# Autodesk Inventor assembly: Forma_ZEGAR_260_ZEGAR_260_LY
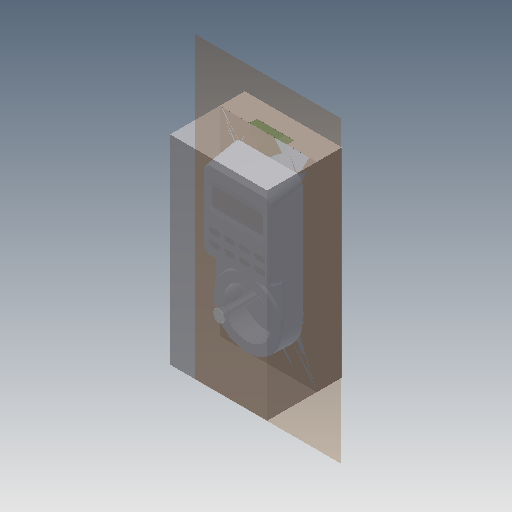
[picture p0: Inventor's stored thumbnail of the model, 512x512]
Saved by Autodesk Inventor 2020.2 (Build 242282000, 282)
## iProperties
Created: 2015-01
Part Number: Forma_ZEGAR_260_ZEGAR_260_LY
Document SubType Name: Assembly
Designer: F.Stasiak
Catalog Web Link: www.expertbooks.pl
Manager: www.cadconsulting.pl
Company: Fabian Stasiak CAD Consulting
Author: F.Stasiak
Subject: Zbiór ćwiczeń. Autodesk Inventor 2020. Kurs Professional
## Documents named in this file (2)
- C:\2020_Kurs_Professional\R6 Formy\Komponenty\Forma_ZEGAR_260_ZEGAR_260_LY.iam
- C:\2020_Kurs_Professional\R6 Formy\Komponenty\Forma_ZEGAR_260_ZEGAR_260_PZ.iam
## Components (1 placed, 1 different names)
1. Forma_ZEGAR_260_ZEGAR_260_PZ:1 [sub-assembly] — Równoległy:28, Równoległy:29, Równoległy:30
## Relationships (3: Flush 3)
- Równoległy:28 [Flush]: Forma_ZEGAR_260_ZEGAR_260_PZ:1
- Równoległy:29 [Flush]: Forma_ZEGAR_260_ZEGAR_260_PZ:1
- Równoległy:30 [Flush]: Forma_ZEGAR_260_ZEGAR_260_PZ:1
